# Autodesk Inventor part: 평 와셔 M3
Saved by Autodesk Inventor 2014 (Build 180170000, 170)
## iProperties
Created: 2025-09
Part Number: 평 와셔 M3
Material: 일반
Document SubType Name: Modeling
Designer: dg
Density: 1 g/cm^3
Appearance: 기본값
Author: dg
Author: jhkim
Description: 평면 와셔
Creation Date: 2025-09-02
Sending System: Autodesk Inventor 2026
Preprocessor: ST-DEVELOPER v20.1
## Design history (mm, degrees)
node "평 와셔 M31"
body "Solid1"
node "기준1"
